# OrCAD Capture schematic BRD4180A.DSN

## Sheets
1 03: I/O Port Connections: size A3; title: EFR32xG21 2.4 GHz 20 dBm Radio Board; rev: A02; company: Silicon Labs; note: BRD4180A; note: JSH; note: JNO
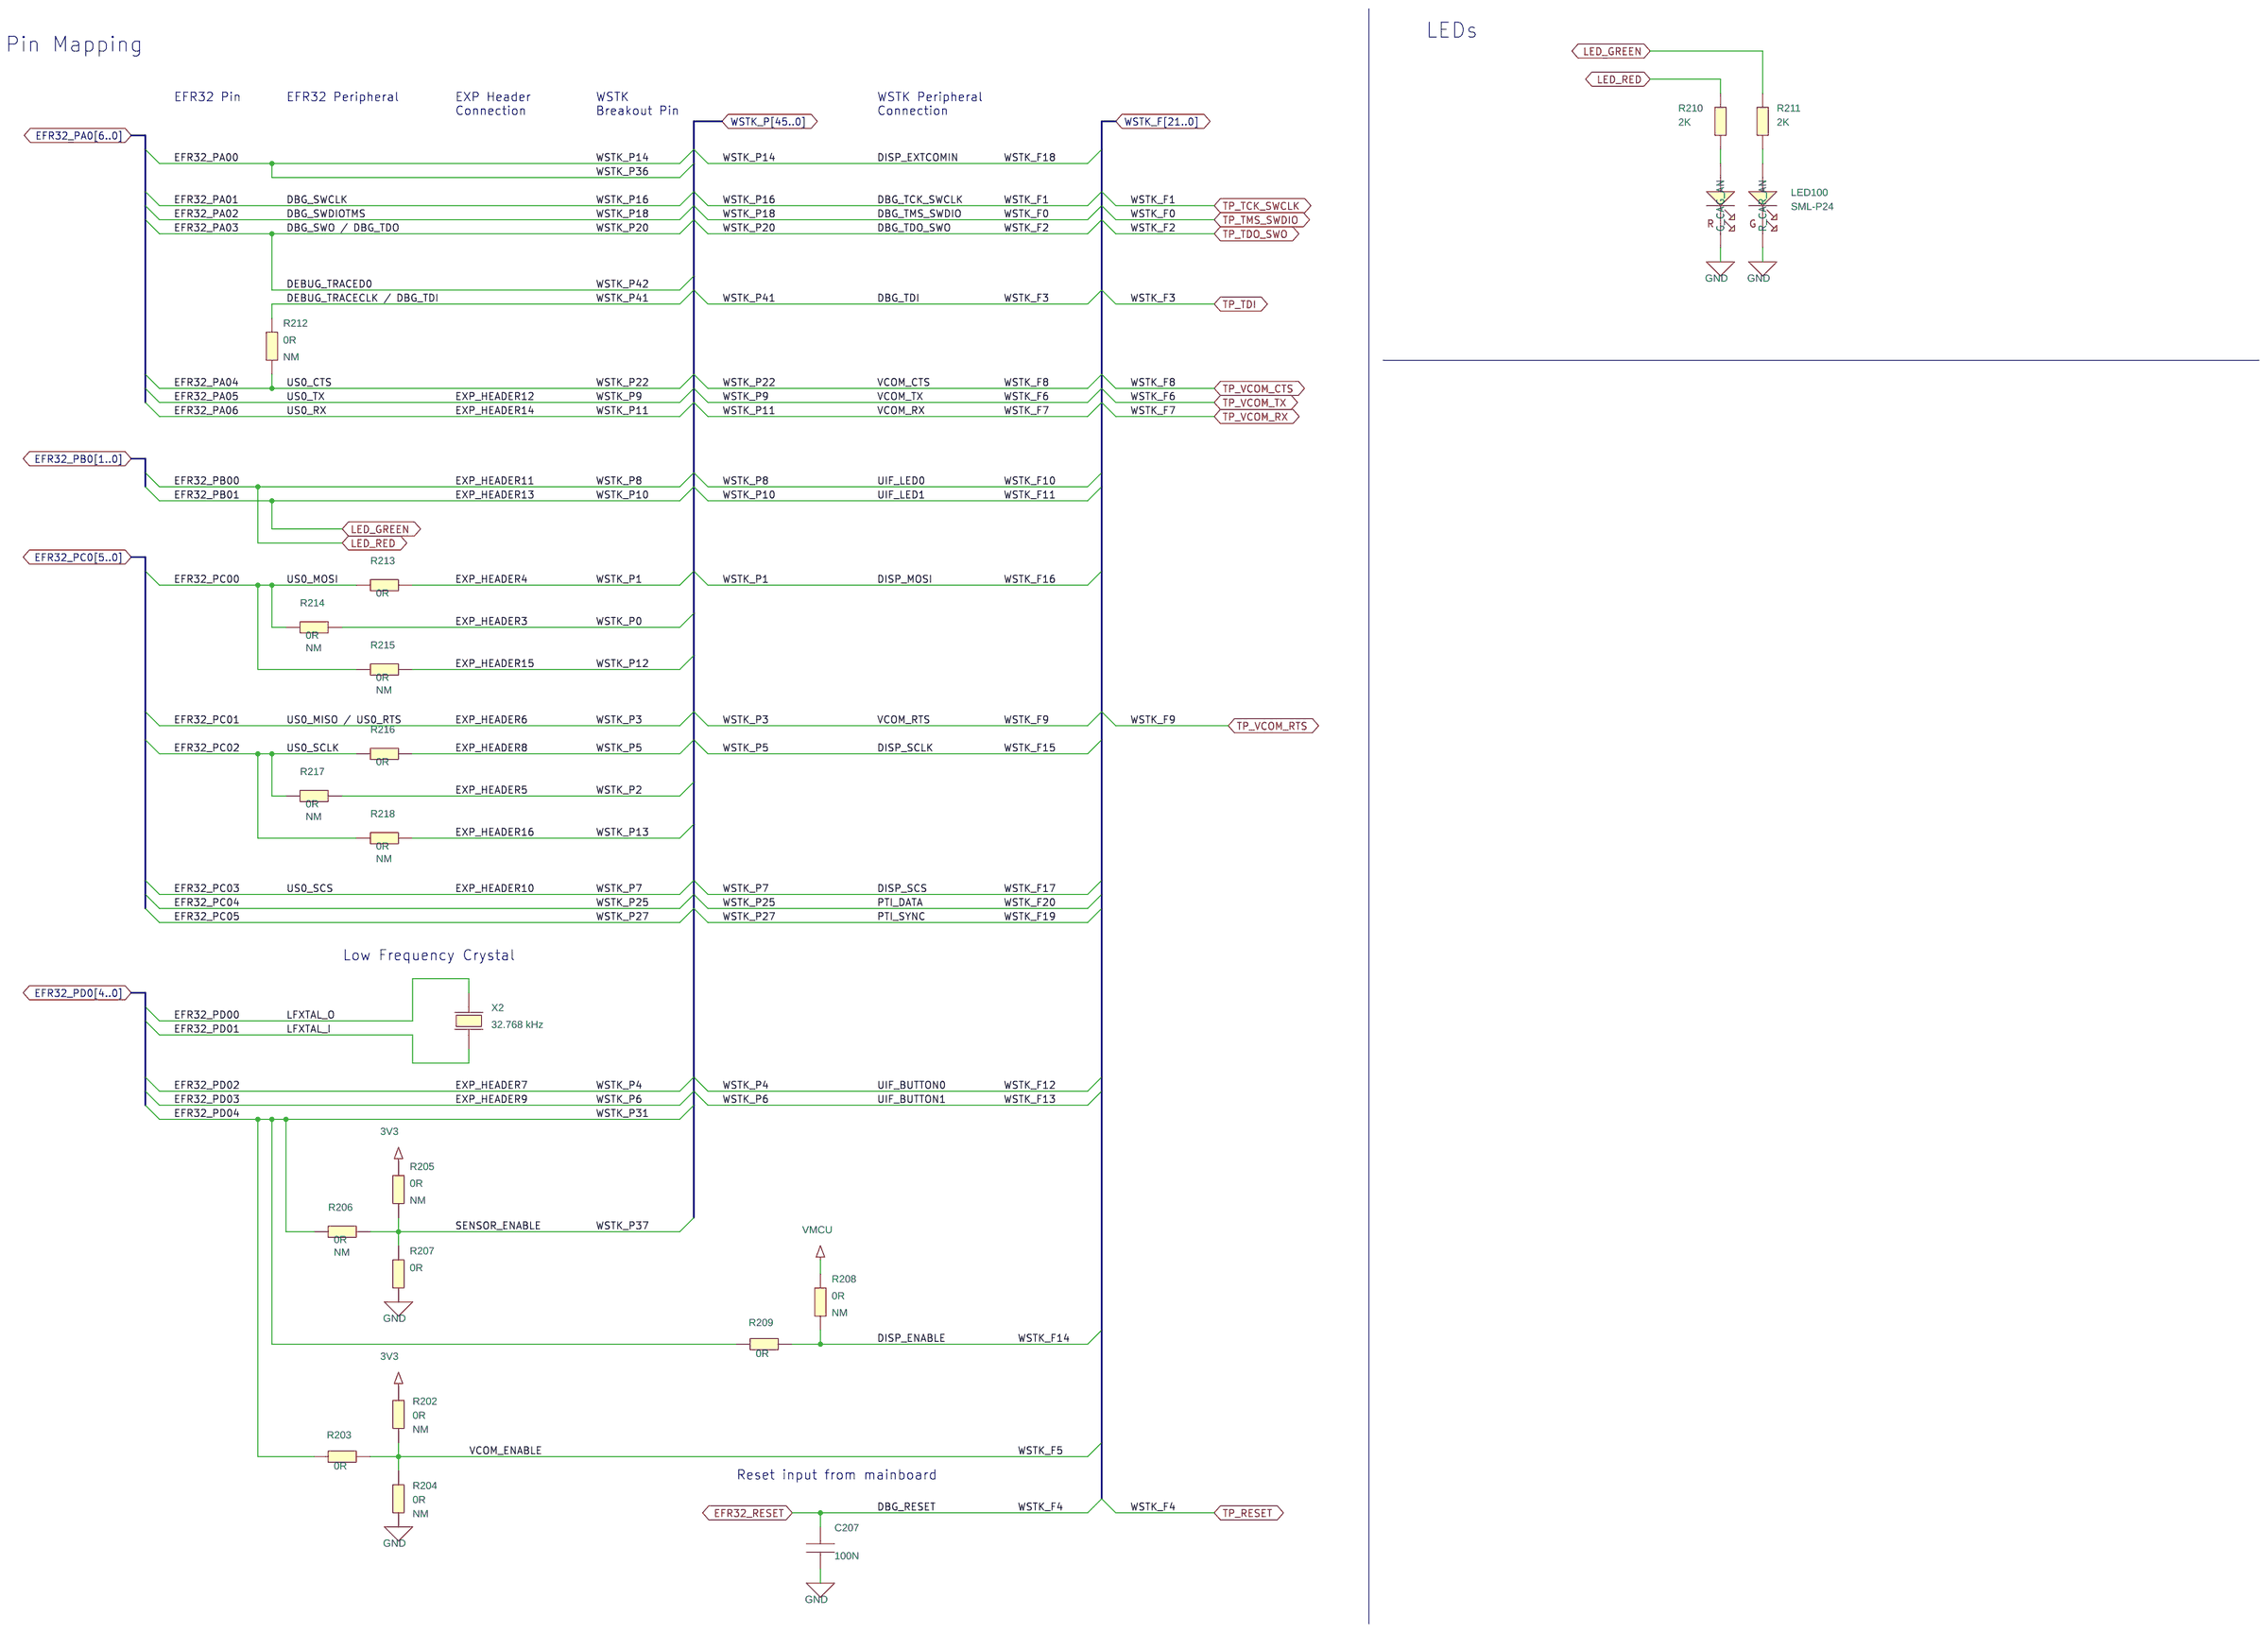
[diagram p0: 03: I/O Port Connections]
2 01: Title Page
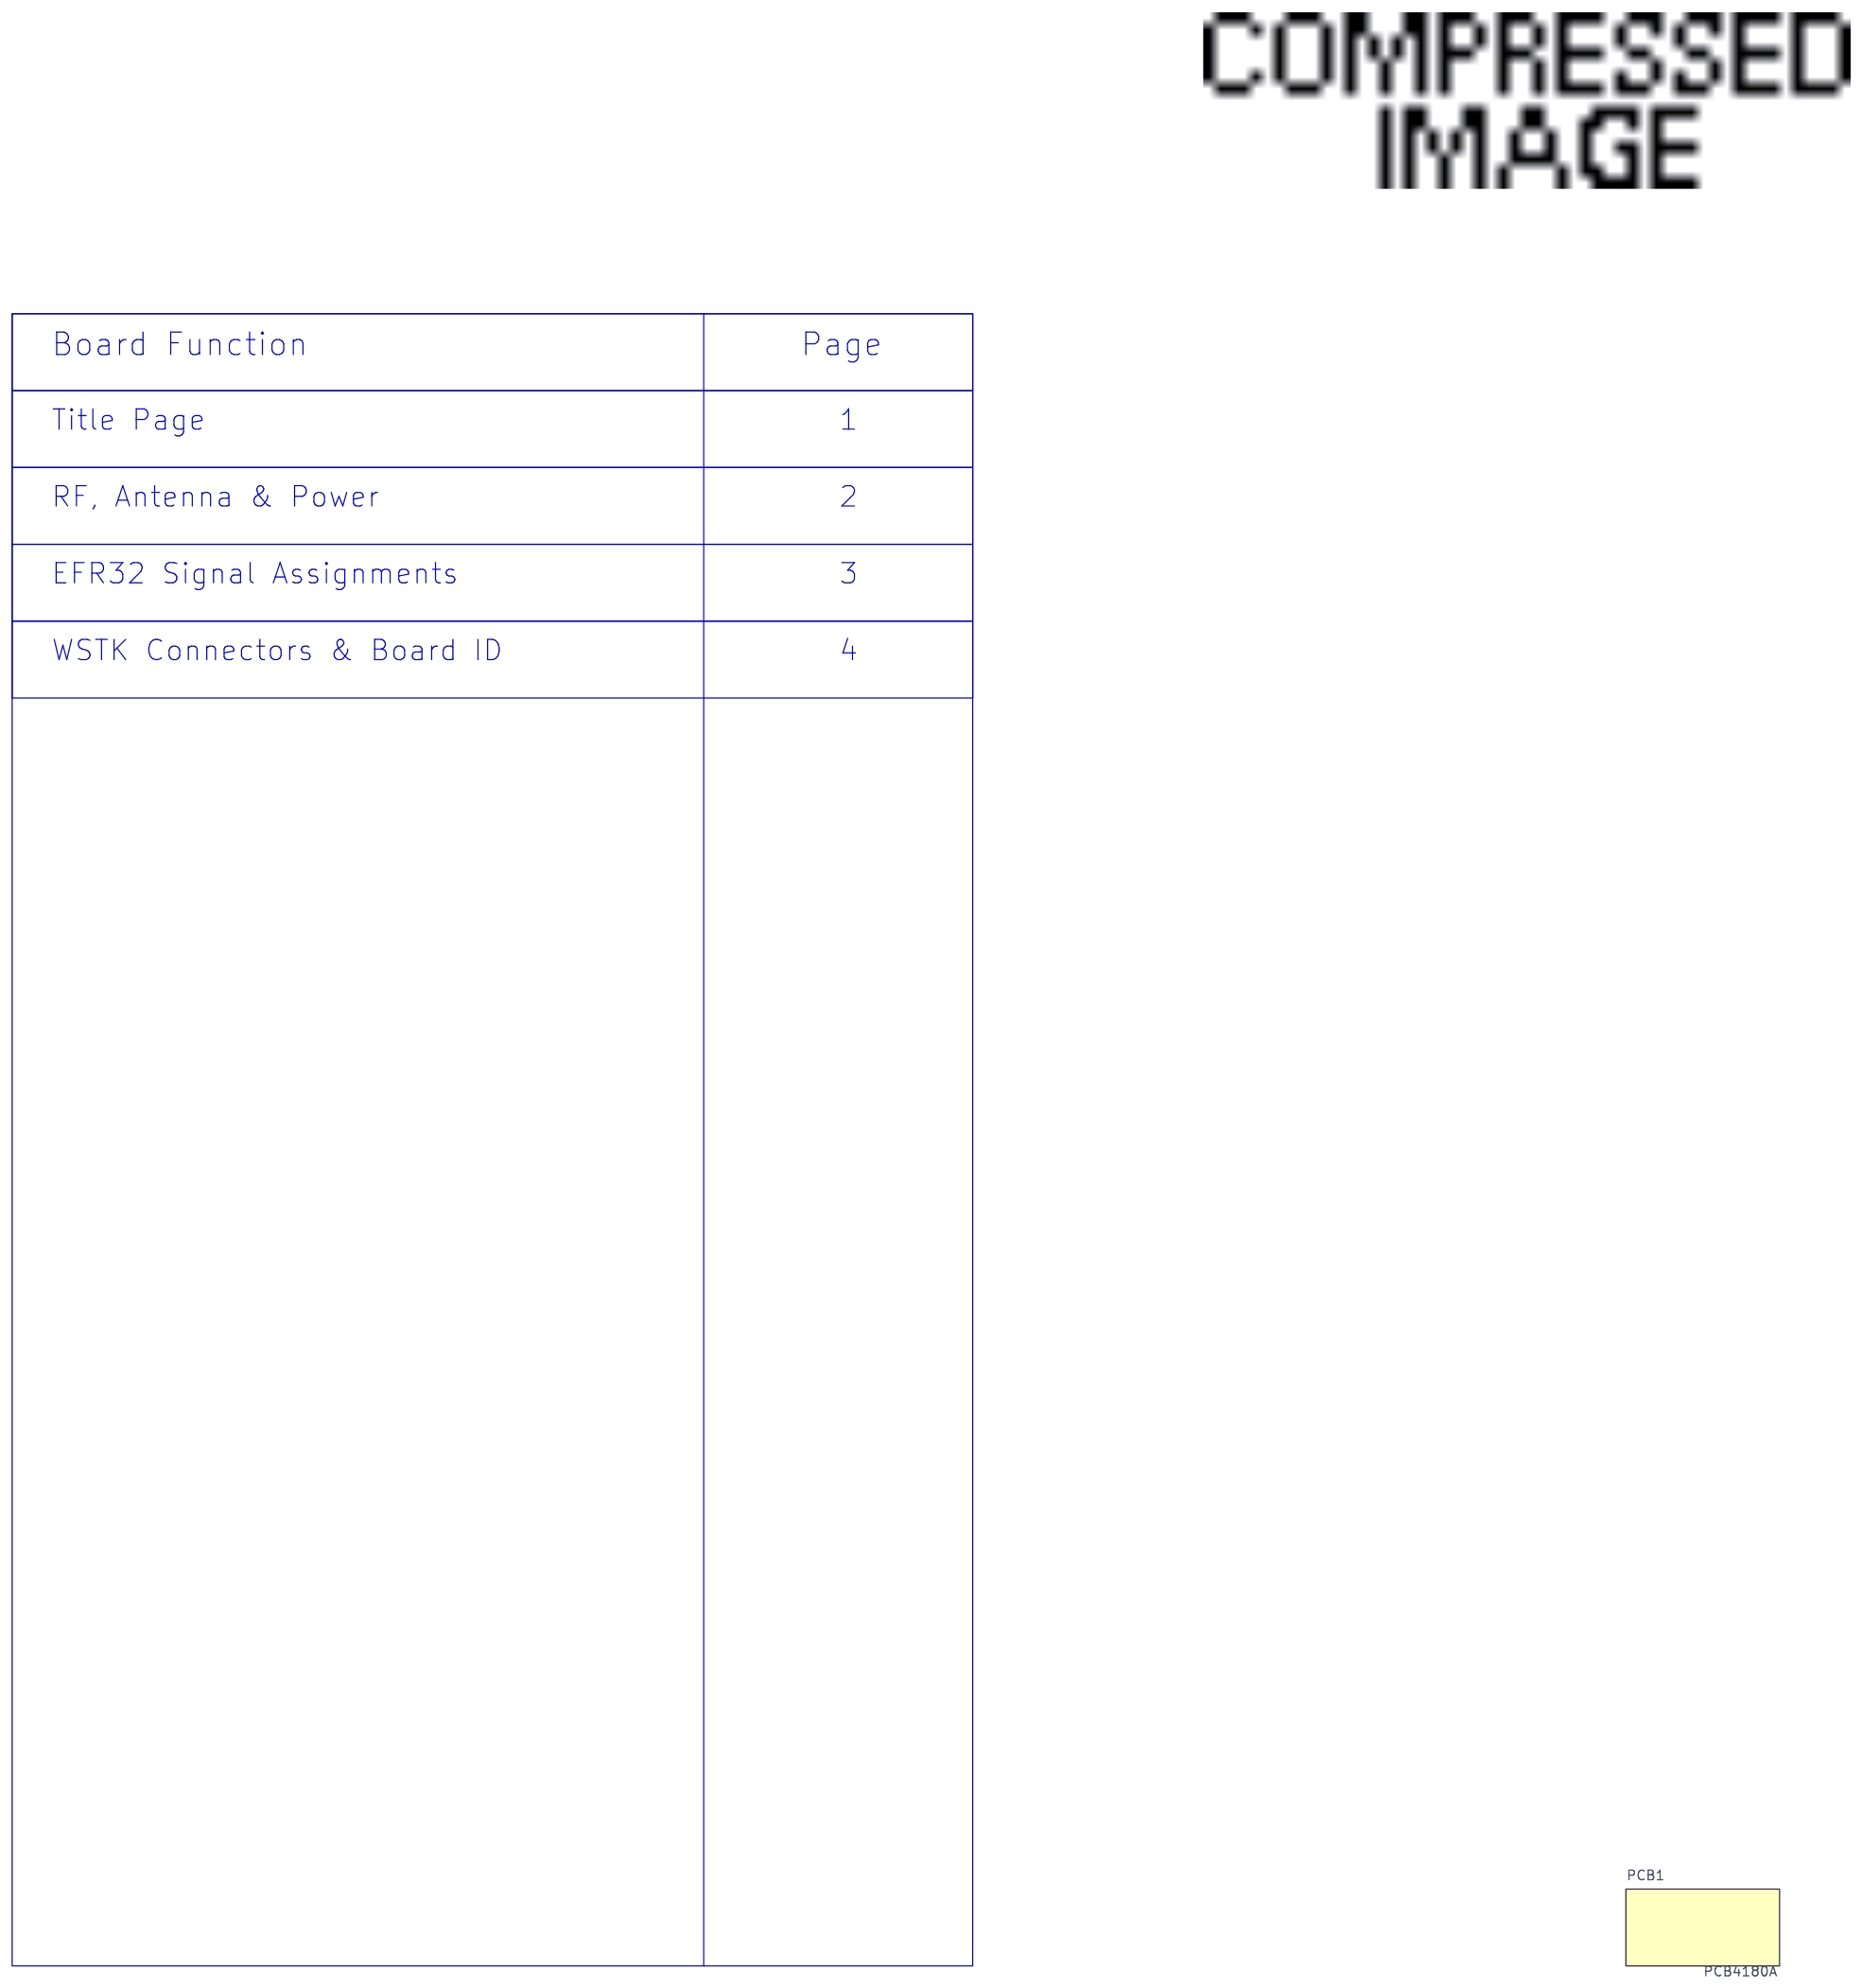
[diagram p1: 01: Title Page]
3 02: RF, Antenna and Power: size A3
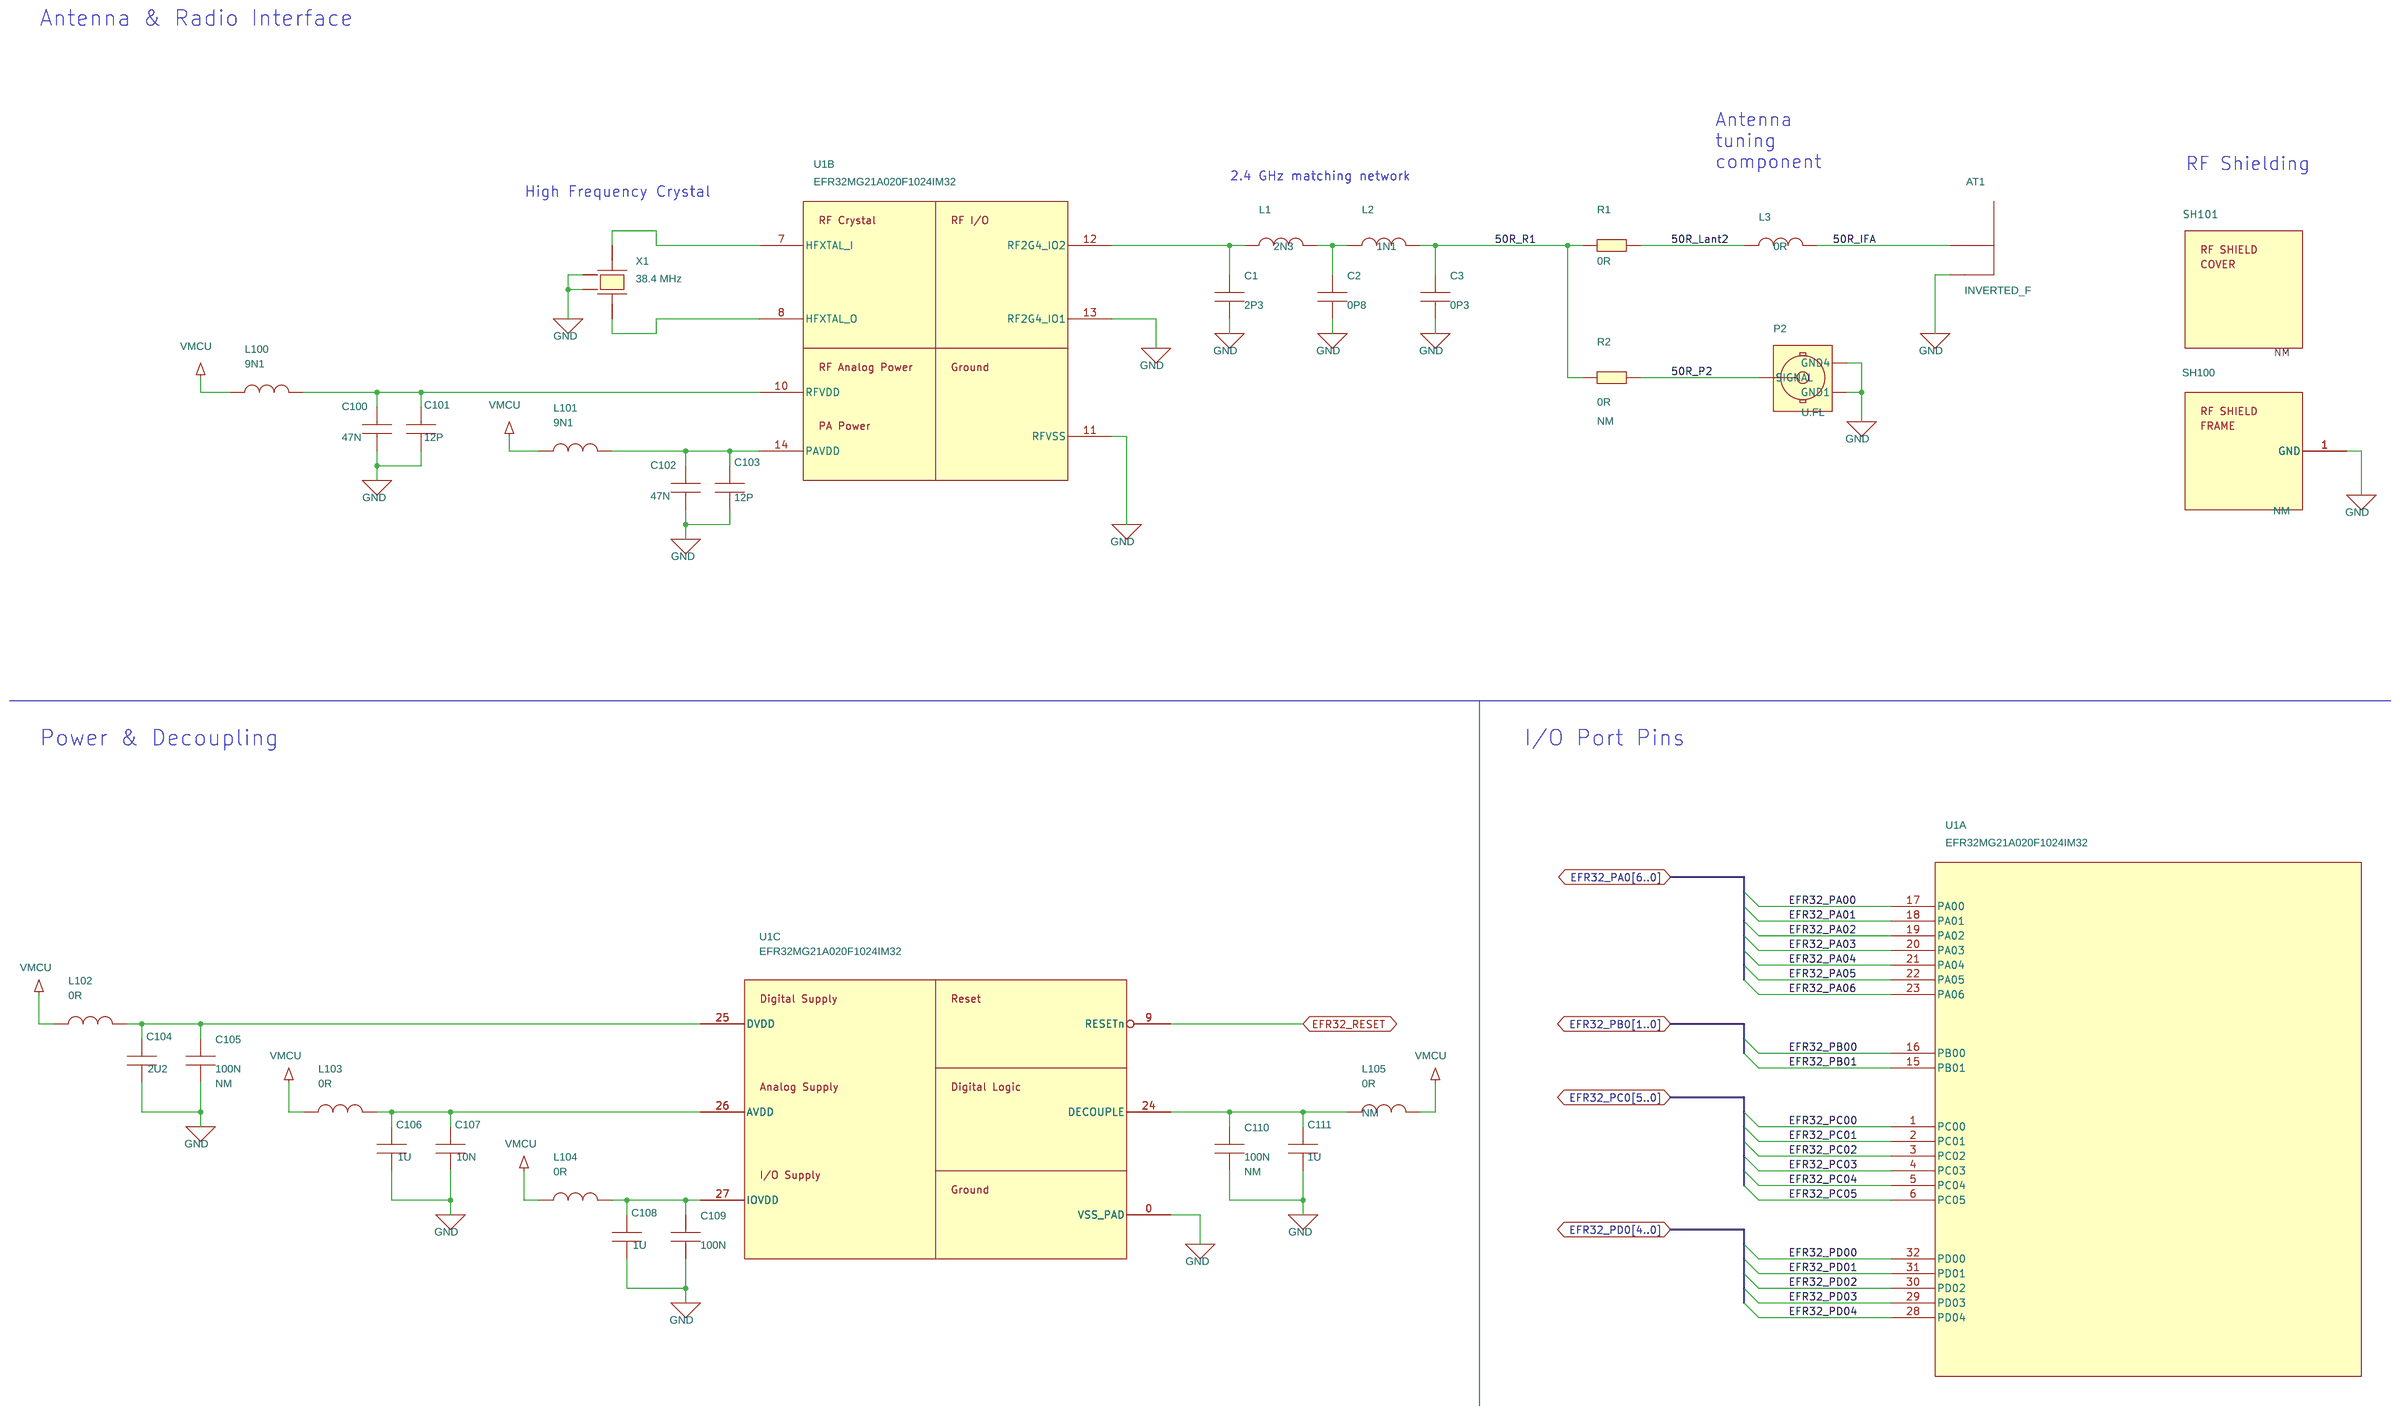
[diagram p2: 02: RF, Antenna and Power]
4 04: WSTK Connectors & Board ID: size A3
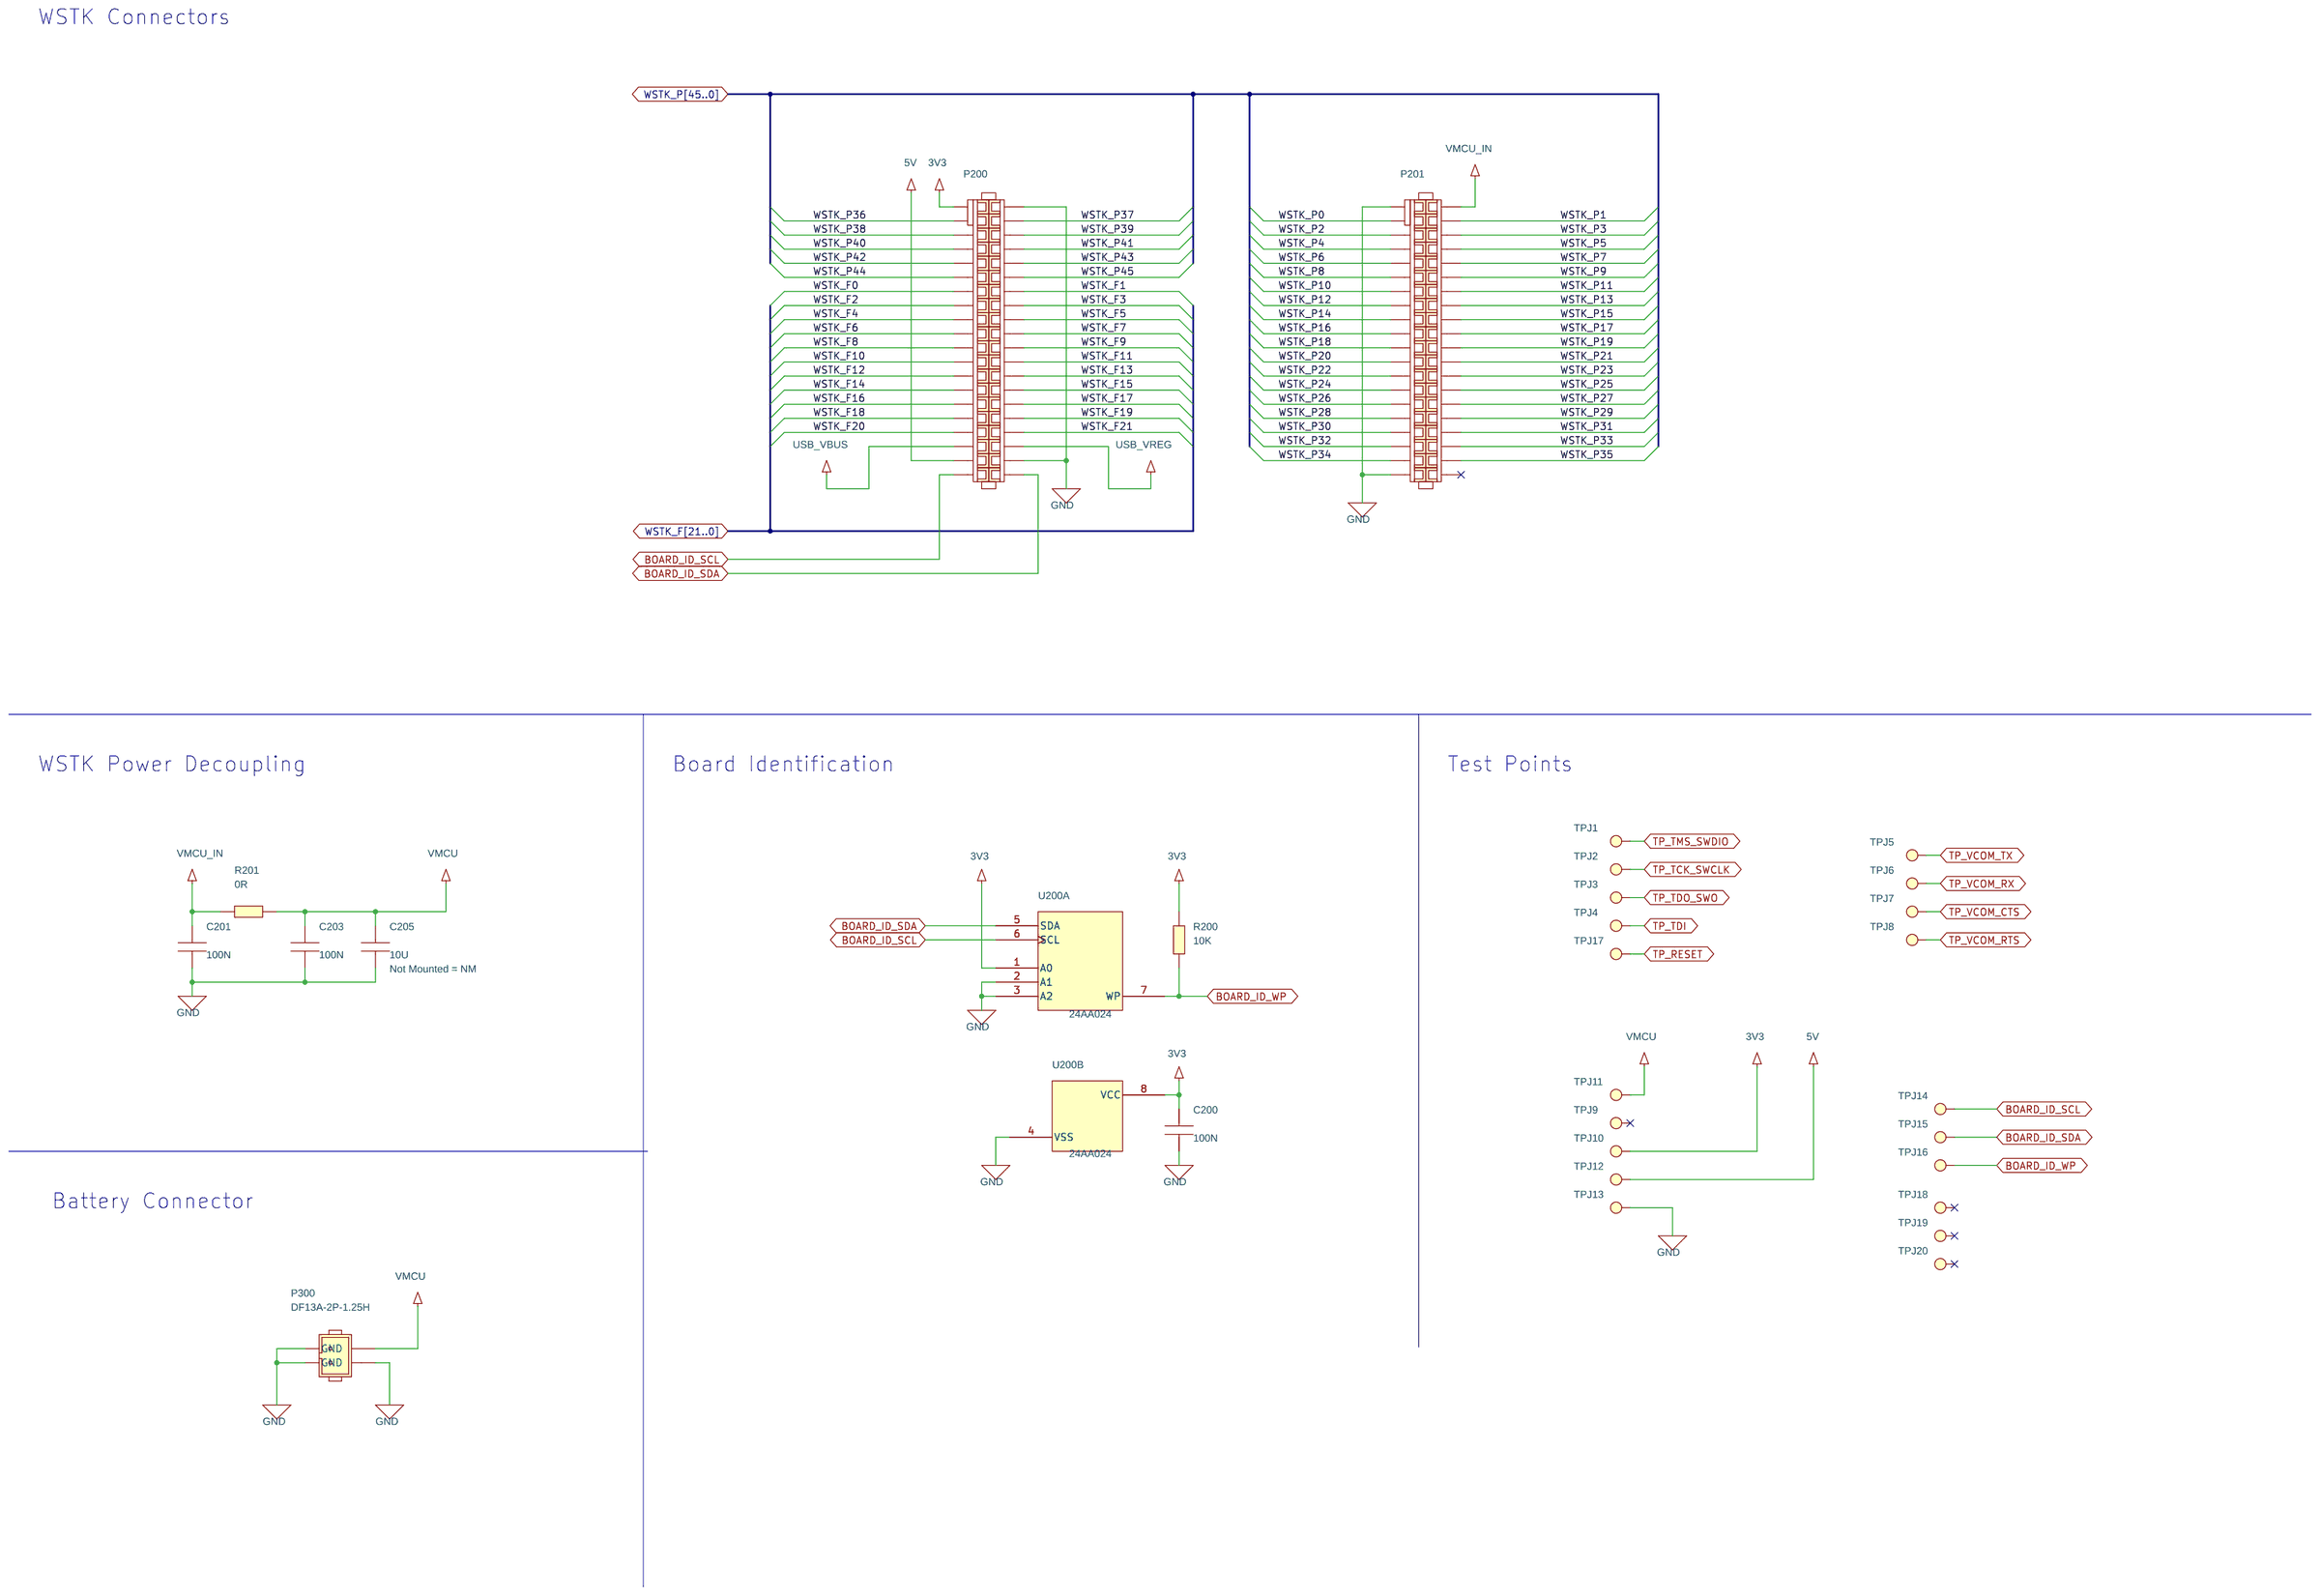
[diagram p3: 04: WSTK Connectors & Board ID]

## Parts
sheet 01: Title Page
PCB1  PCB4180A  [N/A]
sheet 02: RF, Antenna and Power
AT1  INVERTED_F  [EM358x_INVERTED_F]
C1  2P3  [C0201_L]
C2  0P8  [C0201_L]
C3  0P3  [C0201_L]
C100  47N  [C0402_L]
C101  12P  [C0402_L]
C102  47N  [C0402_L]
C103  12P  [C0402_L]
C104  2U2  [C0402_L]
C105  100N  [C0402_L]
C106  1U  [C0402_L]
C107  10N  [C0402_L]
C108  1U  [C0402_L]
C109  100N  [C0402_L]
C110  100N  [C0402_L]
C111  1U  [C0402_L]
L1  2N3  [COIL_0201_L]
L2  1N1  [COIL_0201_L]
L3  0R  [COIL_0402_L]
L100  9N1  [COIL_0402_L]
L101  9N1  [COIL_0402_L]
L102  0R  [COIL_0402_L]
L103  0R  [COIL_0402_L]
L104  0R  [COIL_0402_L]
L105  0R  [COIL_0402_L]
P2  U.FL  [COAX_HIROSE_U.FL_CL331-0471]
R1  0R  [R0402_L]
R2  0R  [R0402_L]
SH100  RF_SHIELD_FRAME_BMI-S-202-F  [Laird_BMI-S-202-F]
SH101  RF_SHIELD_COVER_BMI-S-202-C
U1  EFR32MG21A020F1024IM32  [QFN32_M040_4.0X4.0_EP_SL]  (sections A,B,C)
X1  38.4 MHz  [KDS_DSX211SH_2016]
sheet 03: I/O Port Connections
C207  100N  [C0402_L]
LED100  SML-P24  [LED_ROHM_SML-P24]
R202  0R  [R0402_L]
R203  0R  [R0402_L]
R204  0R  [R0402_L]
R205  0R  [R0402_L]
R206  0R  [R0402_L]
R207  0R  [R0402_L]
R208  0R  [R0402_L]
R209  0R  [R0402_L]
R210  2K  [R0402_L]
R211  2K  [R0402_L]
R212  0R  [R0402_L]
R213  0R  [R0402_L]
R214  0R  [R0402_L]
R215  0R  [R0402_L]
R216  0R  [R0402_L]
R217  0R  [R0402_L]
R218  0R  [R0402_L]
X2  32.768 kHz  [X_MCS_CM8V-T1A]
sheet 04: WSTK Connectors & Board ID
C200  100N  [C0402_L]
C201  100N  [C0402_L]
C203  100N  [C0402_L]
C205  10U  [C0805_L]
P200  SOCKET_2X20_1.27MM_SMD  [SAMTEC_SFC-120-T2-L-D-A]
P201  SOCKET_2X20_1.27MM_SMD  [SAMTEC_SFC-120-T2-L-D-A]
P300  DF13A-2P-1.25H  [Header_DF13A-2P-1.25H]
R200  10K  [R0402_L]
R201  0R  [R0402_L]
TPJ1  TPJ_SMD  [TP_1.0_SMD]
TPJ2  TPJ_SMD  [TP_1.0_SMD]
TPJ3  TPJ_SMD  [TP_1.0_SMD]
TPJ4  TPJ_SMD  [TP_1.0_SMD]
TPJ5  TPJ_SMD  [TP_1.0_SMD]
TPJ6  TPJ_SMD  [TP_1.0_SMD]
TPJ7  TPJ_SMD  [TP_1.0_SMD]
TPJ8  TPJ_SMD  [TP_1.0_SMD]
TPJ9  TPJ_SMD  [TP_1.0_SMD]
TPJ10  TPJ_SMD  [TP_1.0_SMD]
TPJ11  TPJ_SMD  [TP_1.0_SMD]
TPJ12  TPJ_SMD  [TP_1.0_SMD]
TPJ13  TPJ_SMD  [TP_1.0_SMD]
TPJ14  TPJ_SMD  [TP_1.0_SMD]
TPJ15  TPJ_SMD  [TP_1.0_SMD]
TPJ16  TPJ_SMD  [TP_1.0_SMD]
TPJ17  TPJ_SMD  [TP_1.0_SMD]
TPJ18  TPJ_SMD  [TP_1.0_SMD]
TPJ19  TPJ_SMD  [TP_1.0_SMD]
TPJ20  TPJ_SMD  [TP_1.0_SMD]
U200  24AA024  [8-TDFN]  (sections A,B)

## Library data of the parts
PCB1 = PCB: Mfg #: PCB4180A Rev. A01; Price_1K: 1.0
AT1 = INVERTED_F
C1 = C0201: Mfg: Murata; Mfg #: GRM0335C1H2R3WA01D; Technology: C0G; Tolerance: ±0.05P
C2 = C0201: Mfg: Murata; Mfg #: GRM0335C1HR80WA01D; Technology: C0G; Tolerance: ±0.05P
C3 = C0201: Mfg: Murata; Mfg #: GRM0335C1HR30WA01D; Technology: C0G; Tolerance: ±0.05P
C100 C102 C107 C109 = CAPACITOR: Rating: 16V; Technology: X7R; Tolerance: 10%
C101 C103 = CAPACITOR: Rating: 50V; Technology: C0G; Tolerance: 5%
C104 C106 C108 C111 = CAPACITOR: Rating: 25V; Technology: X5R; Tolerance: 10%
C105 C110 = CAPACITOR: Not Mounted: NM; Rating: 16V; Technology: X7R; Tolerance: 10%
L1 = L0201: Mfg: Murata; Mfg #: LQP03HQ2N3B02D; Tolerance: ±0.1N
L2 = L0201: Mfg: Murata; Mfg #: LQP03HQ1N1W02D; Tolerance: ±0.05N
L3 = INDUCTOR
L100 L101 = L0402: Mfg: Murata; Mfg #: LQG15HN9N1J02D; Tolerance: ±5%
L102-L104 = L0402
L105 = L0402: Not Mounted: NM
P2 = HIROSE_U.FL
R1 = RESISTOR
R2 = RESISTOR: Not Mounted: NM
SH100 = RF_SHIELD_FRAME_BMI-S-202-F: Not Mounted: NM
SH101 = RF_SHIELD_COVER_BMI-S-202-C: Not Mounted: NM
U1 = EFR32xG21-2.4GHZ-QFN32: Mfg #: EFR32MG21A020F1024IM32-BR
X1 = DSX211SH: Mfg: Tai-Saw Technology; Mfg #: TZ3398B; Price_1K: 0.512
C200 C201 C203 C207 = C0402: Rating: 16V; Technology: X7R; Tolerance: 10%
LED100 = LED_ROHM_SML-P24
R202 R204-R206 R208 R212 R214 R215 R217 R218 = R0402: Not Mounted: NM
R200 R201 R203 R207 R209 R213 R216 = R0402
R210 R211 = R0201: Tolerance: 1%
X2 = CM8V-T1A: Mfg: Micro Crystal AG; Mfg #: CM8V-T1A-32.768KHZ-7PF-20PPM-TA-QC
C205 = C0805: Not Mounted: NM; Technology: X5R
P200 P201 = SOCKET_2X20_1.27MM_SMD: Mfg: WCON; Mfg #: 2344-220MS3CUNR4
P300 = HEADER_DF13A-2P-1.25H
TPJ1-TPJ20 = TPJ_SMD
U200 = 24AA024: Mfg #: 24AA024T-I/MNY; Price_1K: 0.26

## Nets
3V3: C200.1 P200.1 R200.2 TPJ10.1(TP) U200.1(A0) U200.8(VCC)
5V: P200.37 TPJ12.1(TP)
GND: AT1.2(GND) C1.2 C2.2 C3.2 C100.2 C101.2 C102.2 C103.2 C104.2 C105.2 C106.2 C107.2 C108.2 C109.2 C110.2 C111.2 C200.2 C201.2 C203.2 C205.2 C207.2 LED100.3(G_CA) LED100.4(R_CA) P2.2(GND1) P2.3(GND4) P200.2 P200.38 P201.1 P201.39 P300.2 P300.3(GND) P300.4(GND) R204.1 R207.2 SH100.1(GND) TPJ13.1(TP) U1.0(VSS_PAD) U1.11(RFVSS) U1.13(RF2G4_IO1) U200.2(A1) U200.3(A2) U200.4(VSS) X1.2 X1.4
50R_IFA: AT1.1(ANT) L3.2
50R_Lant2: L3.1 R1.2
50R_P2: P2.1(SIGNAL) R2.2
50R_R1: C3.1 L2.2 R1.1 R2.1
BOARD_ID_SCL: P200.39 TPJ14.1(TP) U200.6(SCL)
BOARD_ID_SDA: P200.40 TPJ15.1(TP) U200.5(SDA)
BOARD_ID_WP: R200.1 TPJ16.1(TP) U200.7(WP)
EFR32_PA00: P200.3 P200.31 P201.17 U1.17(PA00)
EFR32_PA01: P200.14 P201.19 TPJ2.1(TP) U1.18(PA01)
EFR32_PA02: P200.13 P201.21 TPJ1.1(TP) U1.19(PA02)
EFR32_PA03: P200.9 P200.15 P201.23 TPJ3.1(TP) U1.20(PA03)
EFR32_PA04: P200.21 P201.25 R212.2 TPJ7.1(TP) U1.21(PA04)
EFR32_PA05: P200.19 P201.12 TPJ5.1(TP) U1.22(PA05)
EFR32_PA06: P200.20 P201.14 TPJ6.1(TP) U1.23(PA06)
EFR32_PB00: P200.23 P201.11 R210.1 U1.16(PB00)
EFR32_PB01: P200.24 P201.13 R211.1 U1.15(PB01)
EFR32_PC00: R213.1 R214.1 R215.1 U1.1(PC00)
EFR32_PC01: P200.22 P201.6 TPJ8.1(TP) U1.2(PC01)
EFR32_PC02: R216.1 R217.1 R218.1 U1.3(PC02)
EFR32_PC03: P200.30 P201.10 U1.4(PC03)
EFR32_PC04: P200.33 P201.28 U1.5(PC04)
EFR32_PC05: P200.32 P201.30 U1.6(PC05)
EFR32_PD00: U1.32(PD00) X2.1
EFR32_PD01: U1.31(PD01) X2.2
EFR32_PD02: P200.25 P201.7 U1.30(PD02)
EFR32_PD03: P200.26 P201.9 U1.29(PD03)
EFR32_PD04: P201.34 R203.1 R206.1 R209.1 U1.28(PD04)
EFR32_RESET: C207.1 P200.17 TPJ17.1(TP) U1.9(RESETn)
TP_TDI: P200.8 P200.16 R212.1 TPJ4.1(TP)
USB_VBUS: P200.35
USB_VREG: P200.36
VMCU: C203.1 C205.1 L100.1 L101.1 L102.1 L103.1 L104.1 L105.2 P300.1 R201.2 R202.2 R205.1 R208.1 TPJ11.1(TP)
VMCU_IN: C201.1 P201.2 R201.1
WSTK_F5: P200.18 R202.1 R203.2 R204.2
WSTK_F14: P200.27 R208.2 R209.2
WSTK_F15: P200.28 P201.8 R216.2
WSTK_F16: P200.29 P201.4 R213.2
WSTK_F21: P200.34
WSTK_P0: P201.3 R214.2
WSTK_P2: P201.5 R217.2
WSTK_P12: P201.15 R215.2
WSTK_P13: P201.16 R218.2
WSTK_P15: P201.18
WSTK_P17: P201.20
WSTK_P19: P201.22
WSTK_P21: P201.24
WSTK_P23: P201.26
WSTK_P24: P201.27
WSTK_P26: P201.29
WSTK_P28: P201.31
WSTK_P29: P201.32
WSTK_P30: P201.33
WSTK_P32: P201.35
WSTK_P33: P201.36
WSTK_P34: P201.37
WSTK_P35: P201.38
WSTK_P37: P200.4 R205.2 R206.2 R207.1
WSTK_P38: P200.5
WSTK_P39: P200.6
WSTK_P40: P200.7
WSTK_P43: P200.10
WSTK_P44: P200.11
WSTK_P45: P200.12
N350878: C1.1 L1.1 U1.12(RF2G4_IO2)
N351418: C102.1 C103.1 L101.2 U1.14(PAVDD)
N351750: U1.7(HFXTAL_I) X1.3
N351754: U1.8(HFXTAL_O) X1.1
N657194: LED100.2(G_AN) R210.2
N657198: LED100.1(R_AN) R211.2
N691250: C108.1 C109.1 L104.2 U1.27(IOVDD)
N691286: C104.1 C105.1 L102.2 U1.25(DVDD)
N691370: C106.1 C107.1 L103.2 U1.26(AVDD)
N692267: C110.1 C111.1 L105.1 U1.24(DECOUPLE)
N692925: C100.1 C101.1 L100.2 U1.10(RFVDD)
N826284: C2.1 L1.2 L2.1

Not connected (* = marked no-connect by the designer): P201 40*; TPJ9 1(TP)*; TPJ18 1(TP)*; TPJ19 1(TP)*; TPJ20 1(TP)*

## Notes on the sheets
sheet 1
- LEDs
- Pin Mapping
- EFR32 Pin
- EFR32 Peripheral
- EXP Header
  Connection
- WSTK
  Breakout Pin
- WSTK Peripheral
  Connection
- Low Frequency Crystal
- Reset input from mainboard
sheet 2
- Board Function
- Page
- Title Page
- 1
- RF, Antenna & Power
- 2
- EFR32 Signal Assignments
- 3
- WSTK Connectors & Board ID
- 4
sheet 3
- Antenna & Radio Interface
- Antenna
  tuning
  component
- RF Shielding
- 2.4 GHz matching network
- High Frequency Crystal
- Power & Decoupling
- I/O Port Pins
sheet 4
- WSTK Connectors
- WSTK Power Decoupling
- Board Identification
- Test Points
- Battery Connector
